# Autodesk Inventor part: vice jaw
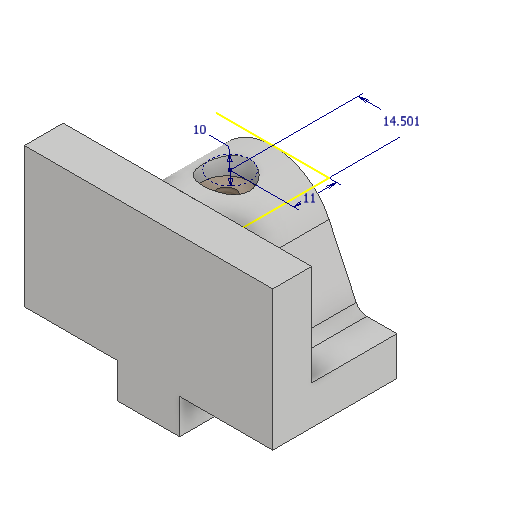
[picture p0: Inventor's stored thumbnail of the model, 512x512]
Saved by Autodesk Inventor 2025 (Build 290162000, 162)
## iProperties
Created: 2016-03
Part Number: vice jaw
Material: Generic
Document SubType Name: Modeling
Designer: Sandeep
Density: 1 g/cm^3
Appearance: Default
Mass: 55.5986 g
Surface Area: 129.526 cm^2
Volume: 55.5986 cm^3
Author: Sandeep
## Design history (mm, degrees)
sketch "Sketch1"
  geometry: L1 (0, 0)-(-32, 0); L2 (-32, 0)-(-32, 36); L3 (-32, 36)-(-22, 36); L4 (-22, 36)-(-22, 10); L5 (-22, 10)-(0, 10); L6 (0, 10)-(0, 0)
  constraints: 12 end point, 5 perpendicular, 1 horizontal
  dimensions: "d0" = 36 distance between parallel lines of L1 L3; "d1" = 32 distance of L1.start L1.end; "d2" = 10 distance of L5.end L1.start; "d3" = 10 distance of L2.end L3.end
extrude "Extrusion1" new body sketch "Sketch1" stored distance "d4" = 64; taper "d5" = 0 deg
sketch "Sketch2"
  geometry: L1 (64, 10)-(64, 0) reference; L2 (64, 10)-(64, 0); L3 (64, 0)-(54.317, 0); L4 (64, 0)-(0, 0) reference; L5 (54.317, 0)-(46.501, -16.762); L6 (0, 0)-(0, 10); L7 (0, 10)-(64, 10); L8 (64, -26)-(0, -26) reference; L9 (0, 0)-(9.683, 0); L10 (32, 10)-(32, -39.451); L11 (9.683, 0)-(17.499, -16.762); A1 r 16 centre (32, -10) between (17.499, -16.762) and (46.501, -16.762); 1 further point
  constraints: 16 end point, 3 point on line, 2 collinear, 2 perpendicular, 2 point on circle, 2 symmetric about line, 2 tangent, 1 centre point, 1 coincident, 1 vertical
  dimensions: "d8" = 16 radius of A1; "d9" = 50 deg angle of L11 L5
extrude "Extrusion2" join sketch "Sketch2" stored distance "d10" = 32; taper "d11" = 0 deg
fillet "Fillet1" dims "d12" = 3
sketch "Sketch3"
  geometry: L1 (40, 0)-(40, 9); L2 (40, 9)-(24, 9); L3 (24, 9)-(24, 0); L4 (24, 0)-(40, 0); L5 (0, 0)-(64, 0) reference; L6 (32, 0)-(32, -54.171)
  constraints: 10 end point, 2 perpendicular, 2 vertical, 1 collinear, 1 point on line, 1 other
  dimensions: "d13" = 16 distance between parallel lines of L3 L1; "d14" = 9 distance of L2.end L3.end
extrude "Extrusion3" join sketch "Sketch3" stored distance "d15" = 32; taper "d16" = 0 deg
sketch "Sketch4"
  geometry: L1 (-24, 19)-(-40, 19) reference; L2 (-32, 19)-(-32, -29.453); C1 r 6 at (-32, -10); A1 r 16 centre (-32, -10) between (-46.501, -16.762) and (-17.499, -16.762) reference; 1 further point
  constraints: 2 end point, 1 centre point, 1 concentric, 1 midpoint, 1 point on line, 1 vertical
  dimensions: "d17" = 12 diameter of C1
extrude "Extrusion4" cut sketch "Sketch4" distance "d18" = 24; taper "d19" = 0 deg
workplane "Work Plane1"
workplane "Work Plane2"
hole "Hole1" diameter "d37" = 4.917; stored, may be unused: countersink angle "d41" = 90 deg, drill point angle "d43" = 118 deg; dims "d35" = 8, "d36" = 8, "d38" = 12, "d39" = 4, "d40" = 2, "d42" = 16
hole "Hole2" diameter "d46" = 4.917; stored, may be unused: countersink angle "d50" = 90 deg, drill point angle "d52" = 118 deg; dims "d44" = 8, "d45" = 8, "d47" = 12, "d48" = 4, "d49" = 2, "d51" = 16
hole "Hole3" diameter "d55" = 4.917; stored, may be unused: countersink angle "d59" = 82 deg, drill point angle "d61" = 118 deg; dims "d53" = 20, "d54" = 32, "d56" = 12, "d57" = 12, "d58" = 5, "d60" = 17.1
body "Solid1"
sketch "Sketch6"
  geometry: 1 further point
sketch "Sketch7"
  geometry: L1 (14.501, 0)-(-14.501, 0) reference; L2 (14.501, 0)-(14.501, -22) reference; C1 r 5 at (0, -11); 1 further point
  constraints: 1 centre point
  dimensions: "d22" = 10 diameter of C1; "d23" = 11 distance from line of L1 C1.centre; "d24" = 14.50092 distance from line of C1.centre L2
sketch "Sketch10"
  geometry: 1 further point
